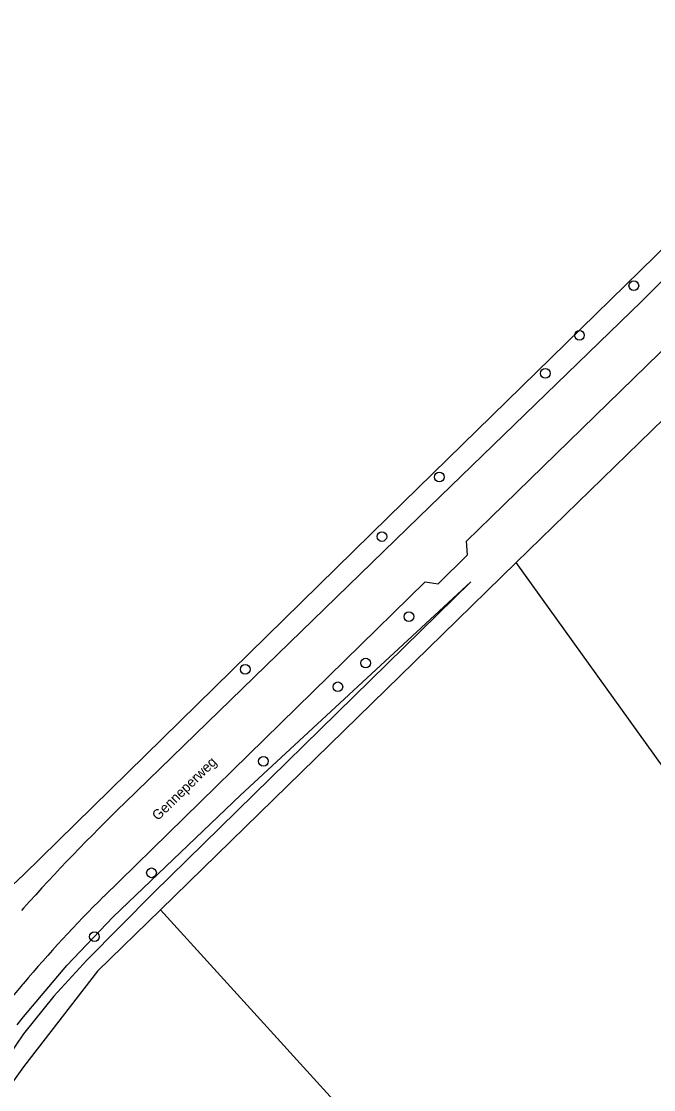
# Model space of a CAD drawing. Extents: x 160203 to 161526, y 379529 to 381797.
# Drawn here: x 160499.8 to 160563.5, y 380192.3 to 380300 of the extents above; entities that cross this region are included whole.
import ezdxf

# ---------------------------------------------------------------- set-up
doc = ezdxf.new("R2010")
doc.units = 0
for name, color, linetype in [('IMGEO_Boom', 7, 'Continuous'), ('IMGEO_Grasland_agrarisch', 7, 'Continuous'), ('IMGEO_Grasland_overig', 7, 'Continuous'), ('IMGEO_Hek', 7, 'Continuous'), ('IMGEO_Loofbos', 7, 'Continuous'), ('IMGEO_Openbare_ruimte_label', 7, 'Continuous'), ('IMGEO_Rijbaan_lokaal_open', 7, 'Continuous'), ('IMGEO_Waterloop', 7, 'Continuous')]:
    doc.layers.add(name, color=color, linetype=linetype)

msp = doc.modelspace()

# ---------------------------------------------------------------- linework, layer by layer
at = {"layer": 'IMGEO_Boom'}
for centre in [(160561.53, 380273.36), (160556.05, 380268.36), (160552.61, 380264.52), (160541.93, 380254.06), (160536.13, 380248.06), (160538.85, 380239.99), (160534.49, 380235.3), (160522.35, 380234.67), (160531.69, 380232.91), (160524.19, 380225.4), (160512.9, 380214.15), (160507.15, 380207.71)]:
    msp.add_circle(centre, 0.489, dxfattribs=at)
at = {"layer": 'IMGEO_Grasland_agrarisch'}
msp.add_lwpolyline([(160488.28, 380202.97), (160500, 380213.96), (160536.75, 380250), (160569.66, 380282.2), (160629.02, 380340.26), (160630.62, 380341.83), (160648.01, 380358.08), (160657.08, 380367.01), (160675.12, 380384.28), (160690.5, 380399.79), (160703.76, 380412.84), (160702.84, 380413.86), (160743.68, 380453.92), (160786.3, 380496.09)], dxfattribs=at)
at = {"layer": 'IMGEO_Grasland_overig'}
for points in [[(160513.81, 380210.43), (160542.25, 380238.2), (160549.68, 380245.45)], [(160513.81, 380210.43), (160507.44, 380204.22), (160500, 380194.58), (160496.44, 380189.66), (160493.08, 380184.15), (160491.35, 380180.94), (160490.5, 380178.18), (160491.03, 380175.47)], [(160593.42, 380174.38), (160564.5, 380154.67), (160513.81, 380210.43)]]:
    msp.add_lwpolyline(points, dxfattribs=at)
at = {"layer": 'IMGEO_Hek'}
msp.add_lwpolyline([(160542.25, 380238.2), (160513.81, 380210.43)], dxfattribs=at)
at = {"layer": 'IMGEO_Loofbos'}
for points in [[(160549.68, 380245.45), (160570.8, 380266.01)], [(160569.39, 380217.98), (160549.68, 380245.45)]]:
    msp.add_lwpolyline(points, dxfattribs=at)
at = {"layer": 'IMGEO_Rijbaan_lokaal_open'}
for points in [[(160780.47, 380484.65), (160750.16, 380455.12), (160747.47, 380455.4), (160745.68, 380453.36), (160745.87, 380450.92), (160709.26, 380414.82), (160707.02, 380415.54), (160701.7, 380410.43), (160702.25, 380407.88), (160634.26, 380342.09), (160632.26, 380342.12), (160629.86, 380339.44), (160630.06, 380337.97), (160566.52, 380275.92), (160562.31, 380271.78), (160539.87, 380250), (160510.21, 380221.21)], [(160508.08, 380211.76), (160540.5, 380243.5), (160541.79, 380243.31), (160544.77, 380246.23), (160544.67, 380247.58), (160547.14, 380250), (160570.68, 380272.95)], [(160500, 380210.58), (160499.78, 380210.34)], [(160499.91, 380202.88), (160500, 380202.99)]]:
    msp.add_lwpolyline(points, dxfattribs=at)
for centre, radius, start, end in [((160661.87, 380065.31), 217.5, 134.2108, 138.0934), ((160603.27, 380115.91), 135.09, 134.8017, 139.861), ((160602.61, 380116.53), 134.18, 139.9428, 150.6966)]:
    msp.add_arc(centre, radius, start, end, dxfattribs=at)
at = {"layer": 'IMGEO_Waterloop'}
msp.add_lwpolyline([(160499.35, 380198.81), (160500, 380199.64), (160504.38, 380204.81), (160509.04, 380209.73), (160521.89, 380221.98), (160545.1, 380243.49), (160513.11, 380212.12), (160506.37, 380205.33), (160503.05, 380201.73), (160500, 380197.91), (160496.87, 380193.33)], dxfattribs=at)

# ---------------------------------------------------------------- texts
at = {"layer": 'IMGEO_Openbare_ruimte_label'}
msp.add_text('Genneperweg', height=1, rotation=44.2707, dxfattribs=at).set_placement((160513.54, 380219.36))

doc.saveas('drawing.dxf')
